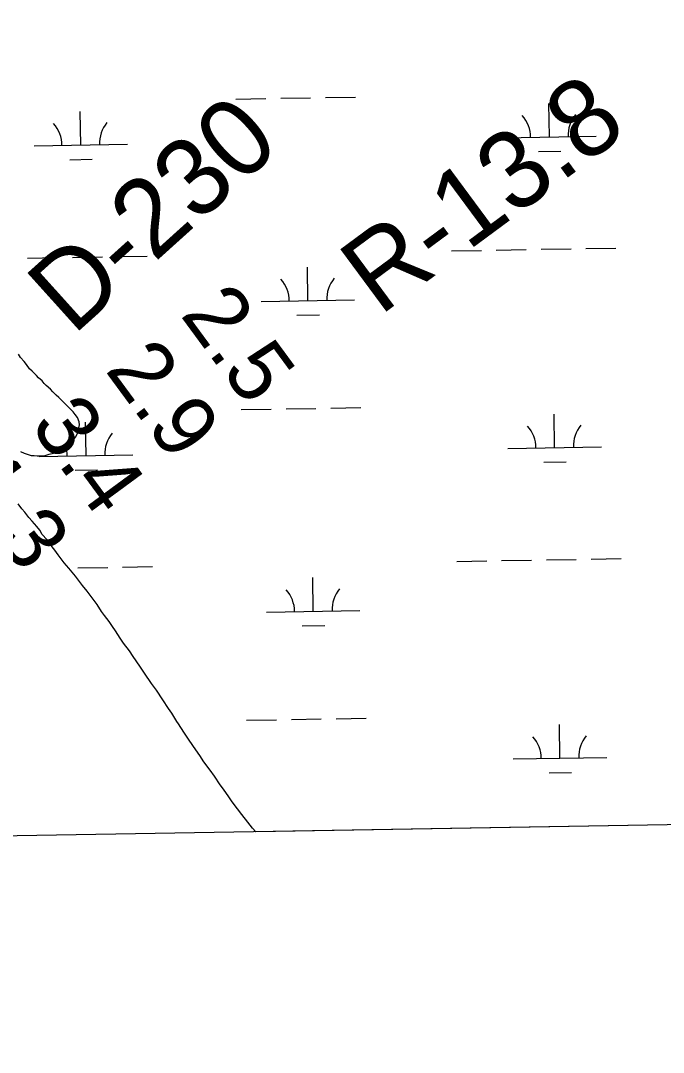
# Model space of a CAD drawing. Extents: x 3887375 to 3925618, y 296674 to 322633.
# Drawn here: x 3905156 to 3905845, y 302106 to 303211 of the extents above; entities that cross this region are included whole.
import ezdxf

# ---------------------------------------------------------------- set-up
doc = ezdxf.new("R2010")
doc.units = 0
for name, color, linetype in [('V-GRID-FRAM', 7, 'Continuous'), ('V-RIVR-RANG', 7, 'Continuous'), ('V-RIVR-RANG-IDEN', 7, 'Continuous'), ('V-WETL-SWMP', 7, 'Continuous')]:
    doc.layers.add(name, color=color, linetype=linetype)

msp = doc.modelspace()

# ---------------------------------------------------------------- linework, layer by layer
at = {"layer": 'V-GRID-FRAM'}
msp.add_lwpolyline([(3891343.3, 320285.8), (3923192.8, 320832.5), (3923512.8, 302652.9), (3891647.4, 302105.9), (3891343.3, 320285.8)], dxfattribs=at)
at = {"layer": 'V-WETL-SWMP'}
for p, q in [((3905386.9, 303126.8), (3905418.9, 303127.4)), ((3905434.9, 303127.7), (3905466.9, 303128.2)), ((3905482.9, 303128.5), (3905514.9, 303129)), ((3905722.5, 303086.2), (3905721.9, 303122.2)), ((3905220.7, 303077.6), (3905220.1, 303113.5)), ((3905672.5, 303085.3), (3905772.5, 303087)), ((3905170.7, 303076.7), (3905270.7, 303078.4)), ((3905710.8, 303070.5), (3905734.8, 303070.9)), ((3905208.9, 303061.9), (3905232.9, 303062.3)), ((3905617.7, 302964.3), (3905649.7, 302964.8)), ((3905665.7, 302965.1), (3905697.7, 302965.7)), ((3905713.7, 302965.9), (3905745.7, 302966.5)), ((3905761.7, 302966.8), (3905793.7, 302967.3)), ((3905163.9, 302956.5), (3905195.9, 302957)), ((3905211.9, 302957.3), (3905243.9, 302957.9)), ((3905259.9, 302958.1), (3905291.9, 302958.7)), ((3905464, 302910.9), (3905463.4, 302946.9)), ((3905414, 302910), (3905514, 302911.8)), ((3905452.3, 302895.3), (3905476.3, 302895.7)), ((3905156.4, 302850), (3905154.2, 302853.5)), ((3905160, 302845.7), (3905156.4, 302850)), ((3905162.6, 302842.7), (3905160, 302845.7)), ((3905165.7, 302837.9), (3905162.6, 302842.7)), ((3905168.8, 302835.3), (3905165.7, 302837.9)), ((3905173.3, 302830.9), (3905168.8, 302835.3)), ((3905175.5, 302828.3), (3905173.3, 302830.9)), ((3905179.5, 302824.9), (3905175.5, 302828.3)), ((3905181.7, 302822.3), (3905179.5, 302824.9)), ((3905183.9, 302820.1), (3905181.7, 302822.3)), ((3905188.3, 302816.2), (3905183.9, 302820.1)), ((3905191, 302813.2), (3905188.3, 302816.2)), ((3905194.5, 302809.7), (3905191, 302813.2)), ((3905197.2, 302807.1), (3905194.5, 302809.7)), ((3905200.7, 302803.7), (3905197.2, 302807.1)), ((3905203, 302801.5), (3905200.7, 302803.7)), ((3905206.9, 302797.6), (3905203, 302801.5)), ((3905210.5, 302794.1), (3905206.9, 302797.6)), ((3905212.7, 302792), (3905210.5, 302794.1)), ((3905214.9, 302788.9), (3905212.7, 302792)), ((3905217.1, 302785.9), (3905214.9, 302788.9)), ((3905392.6, 302794.2), (3905424.6, 302794.8)), ((3905440.6, 302795), (3905472.6, 302795.6)), ((3905488.6, 302795.9), (3905520.6, 302796.4)), ((3905728.2, 302753.5), (3905727.6, 302789.5)), ((3905218.9, 302781.1), (3905217.1, 302785.9)), ((3905218.2, 302773.2), (3905219.4, 302778)), ((3905219.4, 302778), (3905218.9, 302781.1)), ((3905226.4, 302744.9), (3905225.8, 302780.9)), ((3905213, 302761.7), (3905215.2, 302764.8)), ((3905215.2, 302764.8), (3905216.9, 302767.9)), ((3905216.9, 302767.9), (3905218.2, 302773.2)), ((3905198.7, 302751.1), (3905203.5, 302754.2)), ((3905203.5, 302754.2), (3905205.6, 302756.4)), ((3905205.6, 302756.4), (3905209.6, 302759.1)), ((3905209.6, 302759.1), (3905213, 302761.7)), ((3905678.2, 302752.7), (3905778.2, 302754.4)), ((3905156.2, 302749.3), (3905160.2, 302747.6)), ((3905160.2, 302747.6), (3905163.3, 302746.7)), ((3905163.3, 302746.7), (3905167.7, 302745)), ((3905167.7, 302745), (3905170.7, 302745.1)), ((3905170.7, 302745.1), (3905174.2, 302744.7)), ((3905174.2, 302744.7), (3905179.1, 302744.7)), ((3905176.4, 302744.1), (3905276.4, 302745.8)), ((3905179.1, 302744.7), (3905182.6, 302745.2)), ((3905182.6, 302745.2), (3905186.9, 302746.5)), ((3905186.9, 302746.5), (3905191.7, 302747.5)), ((3905191.7, 302747.5), (3905195.2, 302748.8)), ((3905195.2, 302748.8), (3905198.7, 302751.1)), ((3905716.5, 302737.9), (3905740.5, 302738.3)), ((3905214.6, 302729.3), (3905238.6, 302729.7)), ((3905157.8, 302688), (3905153.8, 302693.2)), ((3905160.9, 302684.5), (3905157.8, 302688)), ((3905165.3, 302678.8), (3905160.9, 302684.5)), ((3905168.9, 302674.9), (3905165.3, 302678.8)), ((3905173.8, 302668.9), (3905168.9, 302674.9)), ((3905176.9, 302665), (3905173.8, 302668.9)), ((3905179.5, 302660.6), (3905176.9, 302665)), ((3905184.4, 302655), (3905179.5, 302660.6)), ((3905187.5, 302650.6), (3905184.4, 302655)), ((3905192.9, 302643.7), (3905187.5, 302650.6)), ((3905196.4, 302638.9), (3905192.9, 302643.7)), ((3905203.1, 302630.2), (3905196.4, 302638.9)), ((3905623.4, 302631.7), (3905655.4, 302632.2)), ((3905671.4, 302632.5), (3905703.4, 302633)), ((3905719.4, 302633.3), (3905751.4, 302633.9)), ((3905767.4, 302634.1), (3905799.4, 302634.7)), ((3905208, 302624.6), (3905203.1, 302630.2)), ((3905215.1, 302615.9), (3905208, 302624.6)), ((3905217.6, 302624.7), (3905249.6, 302625.2)), ((3905265.6, 302625.5), (3905297.6, 302626.1)), ((3905222.7, 302605.9), (3905215.1, 302615.9)), ((3905469.7, 302578.3), (3905469.1, 302614.3)), ((3905227.5, 302599.8), (3905222.7, 302605.9)), ((3905234.2, 302591.1), (3905227.5, 302599.8)), ((3905238.2, 302585.5), (3905234.2, 302591.1)), ((3905243.1, 302578.1), (3905238.2, 302585.5)), ((3905246.2, 302573.7), (3905243.1, 302578.1)), ((3905419.8, 302577.4), (3905519.7, 302579.1)), ((3905251.1, 302567.2), (3905246.2, 302573.7)), ((3905254.7, 302562), (3905251.1, 302567.2)), ((3905257.8, 302557.2), (3905254.7, 302562)), ((3905263.1, 302549.4), (3905257.8, 302557.2)), ((3905458, 302562.6), (3905482, 302563)), ((3905266.7, 302544.2), (3905263.1, 302549.4)), ((3905272.9, 302535.9), (3905266.7, 302544.2)), ((3905276.9, 302529.8), (3905272.9, 302535.9)), ((3905284.1, 302519.4), (3905276.9, 302529.8)), ((3905289, 302512), (3905284.1, 302519.4)), ((3905296.5, 302501.1), (3905289, 302512)), ((3905301.9, 302493.7), (3905296.5, 302501.1)), ((3905308.6, 302483.3), (3905301.9, 302493.7)), ((3905314.8, 302474.2), (3905308.6, 302483.3)), ((3905318.4, 302469), (3905314.8, 302474.2)), ((3905323.7, 302460.3), (3905318.4, 302469)), ((3905325.5, 302457.6), (3905323.7, 302460.3)), ((3905331.3, 302449), (3905325.5, 302457.6)), ((3905398.3, 302461.6), (3905430.3, 302462.1)), ((3905446.3, 302462.4), (3905478.3, 302463)), ((3905494.3, 302463.2), (3905526.3, 302463.8)), ((3905733.9, 302420.9), (3905733.3, 302456.9)), ((3905335.3, 302442.4), (3905331.3, 302449)), ((3905341.5, 302433.3), (3905335.3, 302442.4)), ((3905348.2, 302423.7), (3905341.5, 302433.3)), ((3905352.7, 302417.2), (3905348.2, 302423.7)), ((3910283.4, 302425.8), (3905408.1, 302342.1)), ((3905359.3, 302408.1), (3905352.7, 302417.2)), ((3905683.9, 302420.1), (3905783.9, 302421.8)), ((3905363.8, 302401.6), (3905359.3, 302408.1)), ((3905370, 302392.4), (3905363.8, 302401.6)), ((3905722.2, 302405.3), (3905746.2, 302405.7)), ((3905373.6, 302387.7), (3905370, 302392.4)), ((3905379.4, 302379.4), (3905373.6, 302387.7)), ((3905382.9, 302374.2), (3905379.4, 302379.4)), ((3905388.7, 302366.8), (3905382.9, 302374.2)), ((3905393.2, 302360.7), (3905388.7, 302366.8)), ((3905399.8, 302352.5), (3905393.2, 302360.7)), ((3905404.7, 302345.9), (3905399.8, 302352.5)), ((3905408.1, 302342.1), (3905404.7, 302345.9))]:
    msp.add_line(p, q, dxfattribs=at)
for centre, start, end in [((3905667.3, 303085.7), 0.2115, 41.7552), ((3905777.7, 303087.6), 140.2115, 181.7552), ((3905165.4, 303077.1), 0.2115, 41.7552), ((3905275.9, 303079), 140.2115, 181.7552), ((3905408.8, 302910.4), 0.2115, 41.7552), ((3905519.3, 302912.3), 140.2115, 181.7552), ((3905673, 302753.1), 0.2115, 41.7552), ((3905783.4, 302755), 140.2115, 181.7552), ((3905281.6, 302746.4), 140.2115, 181.7552), ((3905171.1, 302744.5), 0.2115, 18.0496), ((3905414.5, 302577.8), 0.2115, 41.7552), ((3905525, 302579.7), 140.2115, 181.7552), ((3905789.1, 302422.3), 140.2115, 181.7552), ((3905678.7, 302420.4), 0.2115, 41.7552)]:
    msp.add_arc(centre, 35.2, start, end, dxfattribs=at)

# ---------------------------------------------------------------- texts
at = {"layer": 'V-RIVR-RANG'}
for s, p in [('2.5', (3905326.5, 302895.8)), ('2.9', (3905246, 302836.6)), ('3.4', (3905165.7, 302777)), ('1.3', (3905085.3, 302717.5))]:
    msp.add_text(s, height=67, rotation=306.3183, dxfattribs=at).set_placement(p)
at = {"layer": 'V-RIVR-RANG-IDEN'}
for s, rotation, p in [('R-13.8', 36.4626, (3905540.7, 302893.8)), ('D-230', 42.0253, (3905212.5, 302872.8))]:
    msp.add_text(s, height=83, rotation=rotation, dxfattribs=at).set_placement(p)

doc.saveas('drawing.dxf')
